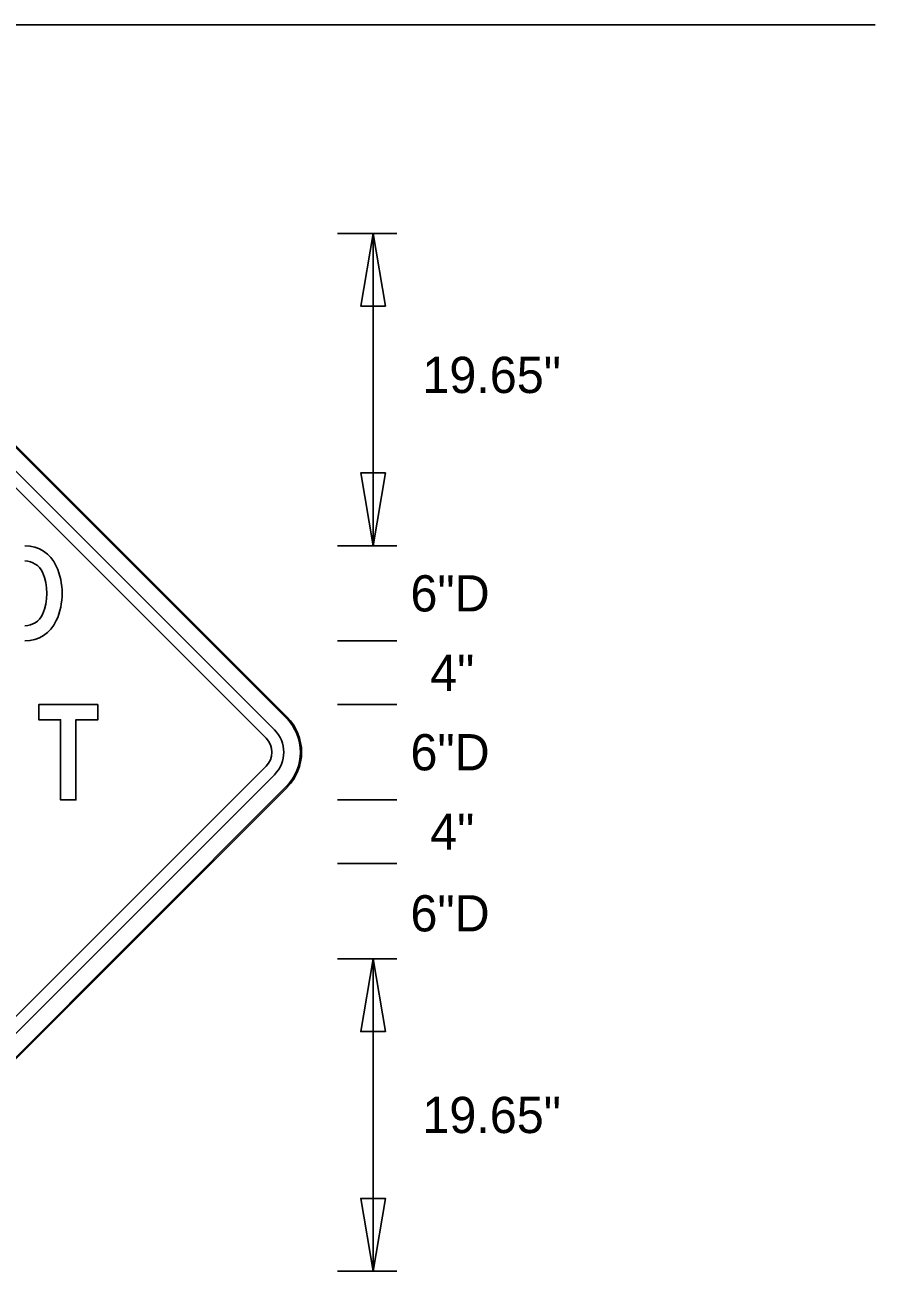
# Model space of a CAD drawing. Extents: x 0 to 770, y 0 to 495.
# Drawn here: x 688 to 770, y 209.7 to 330 of the extents above; entities that cross this region are included whole.
import ezdxf

# ---------------------------------------------------------------- set-up
doc = ezdxf.new("R2010")
doc.units = 0
for name, color, linetype in [('Dimension', 7, 'Continuous'), ('GSBWFill', 7, 'Continuous'), ('GSColorFill', 7, 'Continuous'), ('GSDims', 7, 'Continuous'), ('GSOutline', 7, 'Continuous'), ('SheetLines_dp', 7, 'Continuous'), ('TextStructures', 7, 'Continuous')]:
    doc.layers.add(name, color=color, linetype=linetype)

msp = doc.modelspace()

# ---------------------------------------------------------------- linework, layer by layer
at = {"layer": 'Dimension'}
for points in [[(721.56, 309.87), (720.37, 302.85), (722.75, 302.85)], [(721.56, 279.72), (722.75, 286.74), (720.37, 286.74)], [(721.56, 239.83), (720.37, 232.81), (722.75, 232.81)], [(721.56, 209.69), (722.75, 216.7), (720.37, 216.7)]]:
    msp.add_lwpolyline(points, close=True, dxfattribs=at)
at = {"layer": 'GSBWFill'}
for p, q in [((713.25, 263.17), (667.96, 308.46)), ((712.03, 261.95), (666.74, 307.24)), ((665.92, 306.43), (711.22, 261.13)), ((711.22, 258.42), (665.93, 213.13)), ((666.74, 212.32), (712.03, 257.61)), ((667.96, 211.09), (713.25, 256.39))]:
    msp.add_line(p, q, dxfattribs=at)
msp.add_lwpolyline([(694.99, 264.38), (694.99, 262.91), (692.87, 262.91), (692.87, 255.17), (691.4, 255.17), (691.4, 262.91), (689.28, 262.91), (689.28, 264.38)], close=True, dxfattribs=at)
for centre, radius, start, end in [((687.95, 276.41), 3.31, 23.9411, 90), ((687.95, 276.41), 1.84, 23.9411, 90), ((685.05, 275.12), 5.02, 336.0589, 23.9411), ((685.05, 275.12), 6.49, 336.0589, 23.9411), ((687.95, 273.83), 1.84, 270, 336.0589), ((687.95, 273.83), 3.31, 270, 336.0589), ((709.86, 259.78), 4.79, 315, 45), ((709.86, 259.78), 1.92, 315, 45), ((709.86, 259.78), 3.07, 315, 45)]:
    msp.add_arc(centre, radius, start, end, dxfattribs=at)
at = {"layer": 'GSColorFill'}
for p, q in [((667.87, 308.38), (713.17, 263.09)), ((713.25, 263.17), (667.96, 308.46)), ((713.25, 263.17), (667.96, 308.46)), ((712.03, 261.95), (666.74, 307.24)), ((665.92, 306.43), (711.22, 261.13)), ((711.22, 258.42), (665.93, 213.13)), ((666.74, 212.32), (712.03, 257.61)), ((713.17, 256.47), (667.88, 211.17)), ((667.96, 211.09), (713.25, 256.39)), ((667.96, 211.09), (713.25, 256.39))]:
    msp.add_line(p, q, dxfattribs=at)
msp.add_lwpolyline([(694.99, 264.38), (694.99, 262.91), (692.87, 262.91), (692.87, 255.17), (691.4, 255.17), (691.4, 262.91), (689.28, 262.91), (689.28, 264.38)], close=True, dxfattribs=at)
for centre, radius, start, end in [((687.95, 276.41), 3.31, 23.9411, 90), ((687.95, 276.41), 1.84, 23.9411, 90), ((685.05, 275.12), 5.02, 336.0589, 23.9411), ((685.05, 275.12), 6.49, 336.0589, 23.9411), ((687.95, 273.83), 1.84, 270, 336.0589), ((687.95, 273.83), 3.31, 270, 336.0589), ((709.86, 259.78), 4.68, 315, 45), ((709.86, 259.78), 4.79, 315, 45), ((709.86, 259.78), 4.79, 315, 45), ((709.86, 259.78), 1.92, 315, 45), ((709.86, 259.78), 3.07, 315, 45)]:
    msp.add_arc(centre, radius, start, end, dxfattribs=at)
at = {"layer": 'GSDims'}
for p, q in [((718.11, 309.87), (723.86, 309.87)), ((721.56, 279.72), (721.56, 309.87)), ((718.11, 279.72), (723.86, 279.72)), ((718.11, 279.72), (723.86, 279.72)), ((718.11, 270.52), (723.86, 270.52)), ((718.11, 270.52), (723.86, 270.52)), ((718.11, 264.38), (723.86, 264.38)), ((718.11, 264.38), (723.86, 264.38)), ((718.11, 255.17), (723.86, 255.17)), ((718.11, 255.17), (723.86, 255.17)), ((718.11, 249.04), (723.86, 249.04)), ((718.11, 249.04), (723.86, 249.04)), ((718.11, 239.83), (723.86, 239.83)), ((718.11, 239.83), (723.86, 239.83)), ((721.56, 209.69), (721.56, 239.83)), ((718.11, 209.69), (723.86, 209.69))]:
    msp.add_line(p, q, dxfattribs=at)
at = {"layer": 'GSOutline'}
for p, q in [((713.25, 263.17), (667.96, 308.46)), ((712.03, 261.95), (666.74, 307.24)), ((711.22, 261.13), (665.92, 306.43)), ((665.92, 213.13), (711.22, 258.42)), ((666.74, 212.31), (712.03, 257.61)), ((667.96, 211.09), (713.25, 256.39))]:
    msp.add_line(p, q, dxfattribs=at)
msp.add_lwpolyline([(694.99, 264.38), (694.99, 262.91), (692.87, 262.91), (692.87, 255.17), (691.4, 255.17), (691.4, 262.91), (689.28, 262.91), (689.28, 264.38)], close=True, dxfattribs=at)
for centre, radius, start, end in [((687.95, 276.41), 3.31, 23.9411, 90), ((687.95, 276.41), 1.84, 23.9411, 90), ((685.05, 275.12), 5.02, 336.0589, 23.9411), ((685.05, 275.12), 6.49, 336.0589, 23.9411), ((687.95, 273.83), 1.84, 270, 336.0589), ((687.95, 273.83), 3.31, 270, 336.0589), ((709.86, 259.78), 4.79, 315, 45), ((709.86, 259.78), 1.92, 315, 45), ((709.86, 259.78), 3.07, 315, 45)]:
    msp.add_arc(centre, radius, start, end, dxfattribs=at)
at = {"layer": 'SheetLines_dp'}
msp.add_line((0, 330), (770, 330), dxfattribs=at)

# ---------------------------------------------------------------- texts
at = {"layer": 'TextStructures'}
for s, p in [('19.65"', (726.31, 294.46)), ('6"D', (725.16, 273.37)), ('4"', (727.06, 265.7)), ('6"D', (725.16, 258.03)), ('4"', (727.06, 250.36)), ('6"D', (725.16, 242.48)), ('19.65"', (726.31, 223.01))]:
    msp.add_text(s, height=3.5, dxfattribs=at).set_placement(p)

doc.saveas('drawing.dxf')
